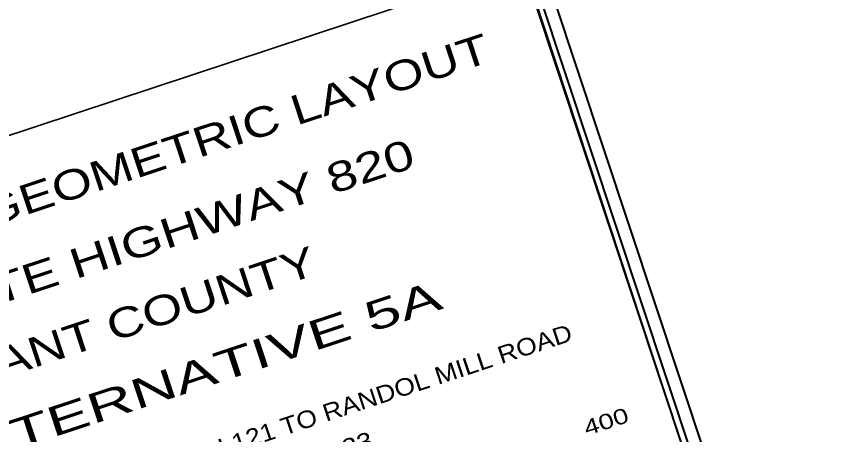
# Model space of a CAD drawing. Extents: x 2355803 to 2371254, y 6970215 to 6985302.
# Drawn here: x 2370614 to 2371254, y 6978644 to 6978973 of the extents above; entities that cross this region are included whole.
import ezdxf

# ---------------------------------------------------------------- set-up
doc = ezdxf.new("R2010")
doc.units = 0
doc.header["$LTSCALE"] = 7.1
doc.layers.add('19', color=7, linetype='Continuous', lineweight=13)
doc.layers.add('8', color=7, linetype='Continuous', lineweight=13)

msp = doc.modelspace()

# ---------------------------------------------------------------- linework, layer by layer
at = {"layer": '19', "lineweight": 40}
msp.add_line((2370164.884, 6981571.274), (2371235.212, 6978343.566), dxfattribs=at)
at = {"layer": '19', "lineweight": 35}
for p in [(2370247.37, 6978760.29), (2371235.212, 6978343.566)]:
    msp.add_line(p, (2371013.89, 6979013.514), dxfattribs=at)
at = {"layer": '8', "lineweight": 40}
for p, q in [((2370177.548, 6981580.742), (2371254, 6978334.567)), ((2370171.204, 6981568.102), (2371241.36, 6978340.911))]:
    msp.add_line(p, q, dxfattribs=at)
at = {"layer": '8', "lineweight": 35}
for p in [(2370247.37, 6978760.29), (2371235.212, 6978343.566)]:
    msp.add_line(p, (2371013.89, 6979013.514), dxfattribs=at)

# ---------------------------------------------------------------- texts
at = {"layer": '19'}
for s, height, width, p in [('PRELIMINARY GEOMETRIC LAYOUT', 23.33, 1.3, (2370319.498, 6978716.852)), ('INTERSTATE HIGHWAY 820', 23.33, 1.35, (2370401.264, 6978680.484)), ('TARRANT COUNTY', 23.33, 1.3, (2370497.66, 6978653.364)), (' HOV ALTERNATIVE 5A', 23.33, 1.6, (2370427.262, 6978570.366)), ('LIMITS:  NORTH INTERCHANGE SH 121 TO RANDOL MILL ROAD', 13.58, 1.15, (2370447.402, 6978518.316)), ('CONTROL NO.  0008-13-123', 13.58, 1.2, (2370624.026, 6978543.906))]:
    msp.add_text(s, height=height, rotation=18.281, dxfattribs=dict(at, width=width)).set_placement(p)
at = {"layer": '8'}
for s, height, width, p in [('PRELIMINARY GEOMETRIC LAYOUT', 23.33, 1.3, (2370319.498, 6978716.852)), ('INTERSTATE HIGHWAY 820', 23.33, 1.35, (2370401.264, 6978680.484)), ('TARRANT COUNTY', 23.33, 1.3, (2370497.66, 6978653.364)), (' HOV ALTERNATIVE 5A', 23.33, 1.6, (2370427.262, 6978570.366)), ('LIMITS:  NORTH INTERCHANGE SH 121 TO RANDOL MILL ROAD', 13.58, 1.15, (2370447.402, 6978518.316)), ('400', 12, 1.35, (2371063.475, 6978643.018)), ('CONTROL NO.  0008-13-123', 13.58, 1.2, (2370624.026, 6978543.906))]:
    msp.add_text(s, height=height, rotation=18.281, dxfattribs=dict(at, width=width)).set_placement(p)

doc.saveas('drawing.dxf')
